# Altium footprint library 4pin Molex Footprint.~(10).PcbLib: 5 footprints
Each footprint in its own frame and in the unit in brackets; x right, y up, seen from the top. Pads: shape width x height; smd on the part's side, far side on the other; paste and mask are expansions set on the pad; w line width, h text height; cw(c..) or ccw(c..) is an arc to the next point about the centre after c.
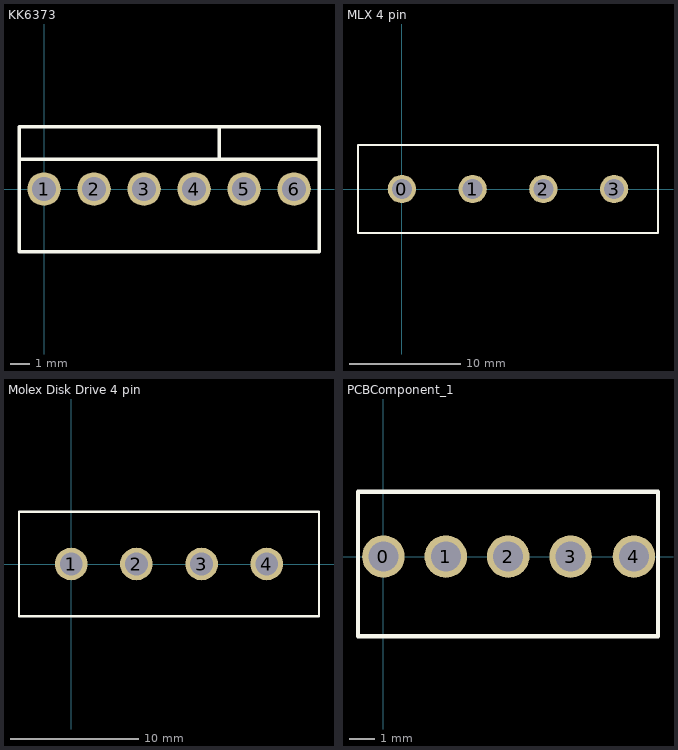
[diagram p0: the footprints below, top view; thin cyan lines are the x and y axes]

## KK6373 [mil]
pads (6):
  round 67 hole 47.24: 1(0,0) 2(100,0) 3(200,0) 4(300,0) 5(400,0) 6(500,0)
Top Overlay:
  lines w7: -50,60 350,60 ; 350,125 350,60 ; 550,60 350,60 ; -50,-125 550,-125 550,125 -50,125 -50,-125

## MLX 4 pin [mil]
pads (4):
  round 100 hole 70: 0(0,0) 1(250,0) 2(500,0) 3(750,0)
Top Overlay:
  lines w7: -155,-155 -155,155 905,155 905,-155 -155,-155

## Molex Disk Drive 4 pin [mil]
pads (4):
  round 100 hole 70: 1(0,0) 2(200,0) 3(400,0) 4(600,0)
Top Overlay:
  lines w7: -160,-160 760,-160 760,160 -160,160 -160,-160

## PCBComponent_1 [mil]
pads (5):
  round 67 hole 47.24: 0(0,0) 1(98.43,0) 2(196.85,0) 3(295.28,0) 4(395,0)
Top Overlay:
  lines w7: -40,-125.98 -40,-100 -40,102.36 433.07,102.36 433.07,-100 433.07,-125.98 -40,-125.98

## Xilinx Header [mil]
